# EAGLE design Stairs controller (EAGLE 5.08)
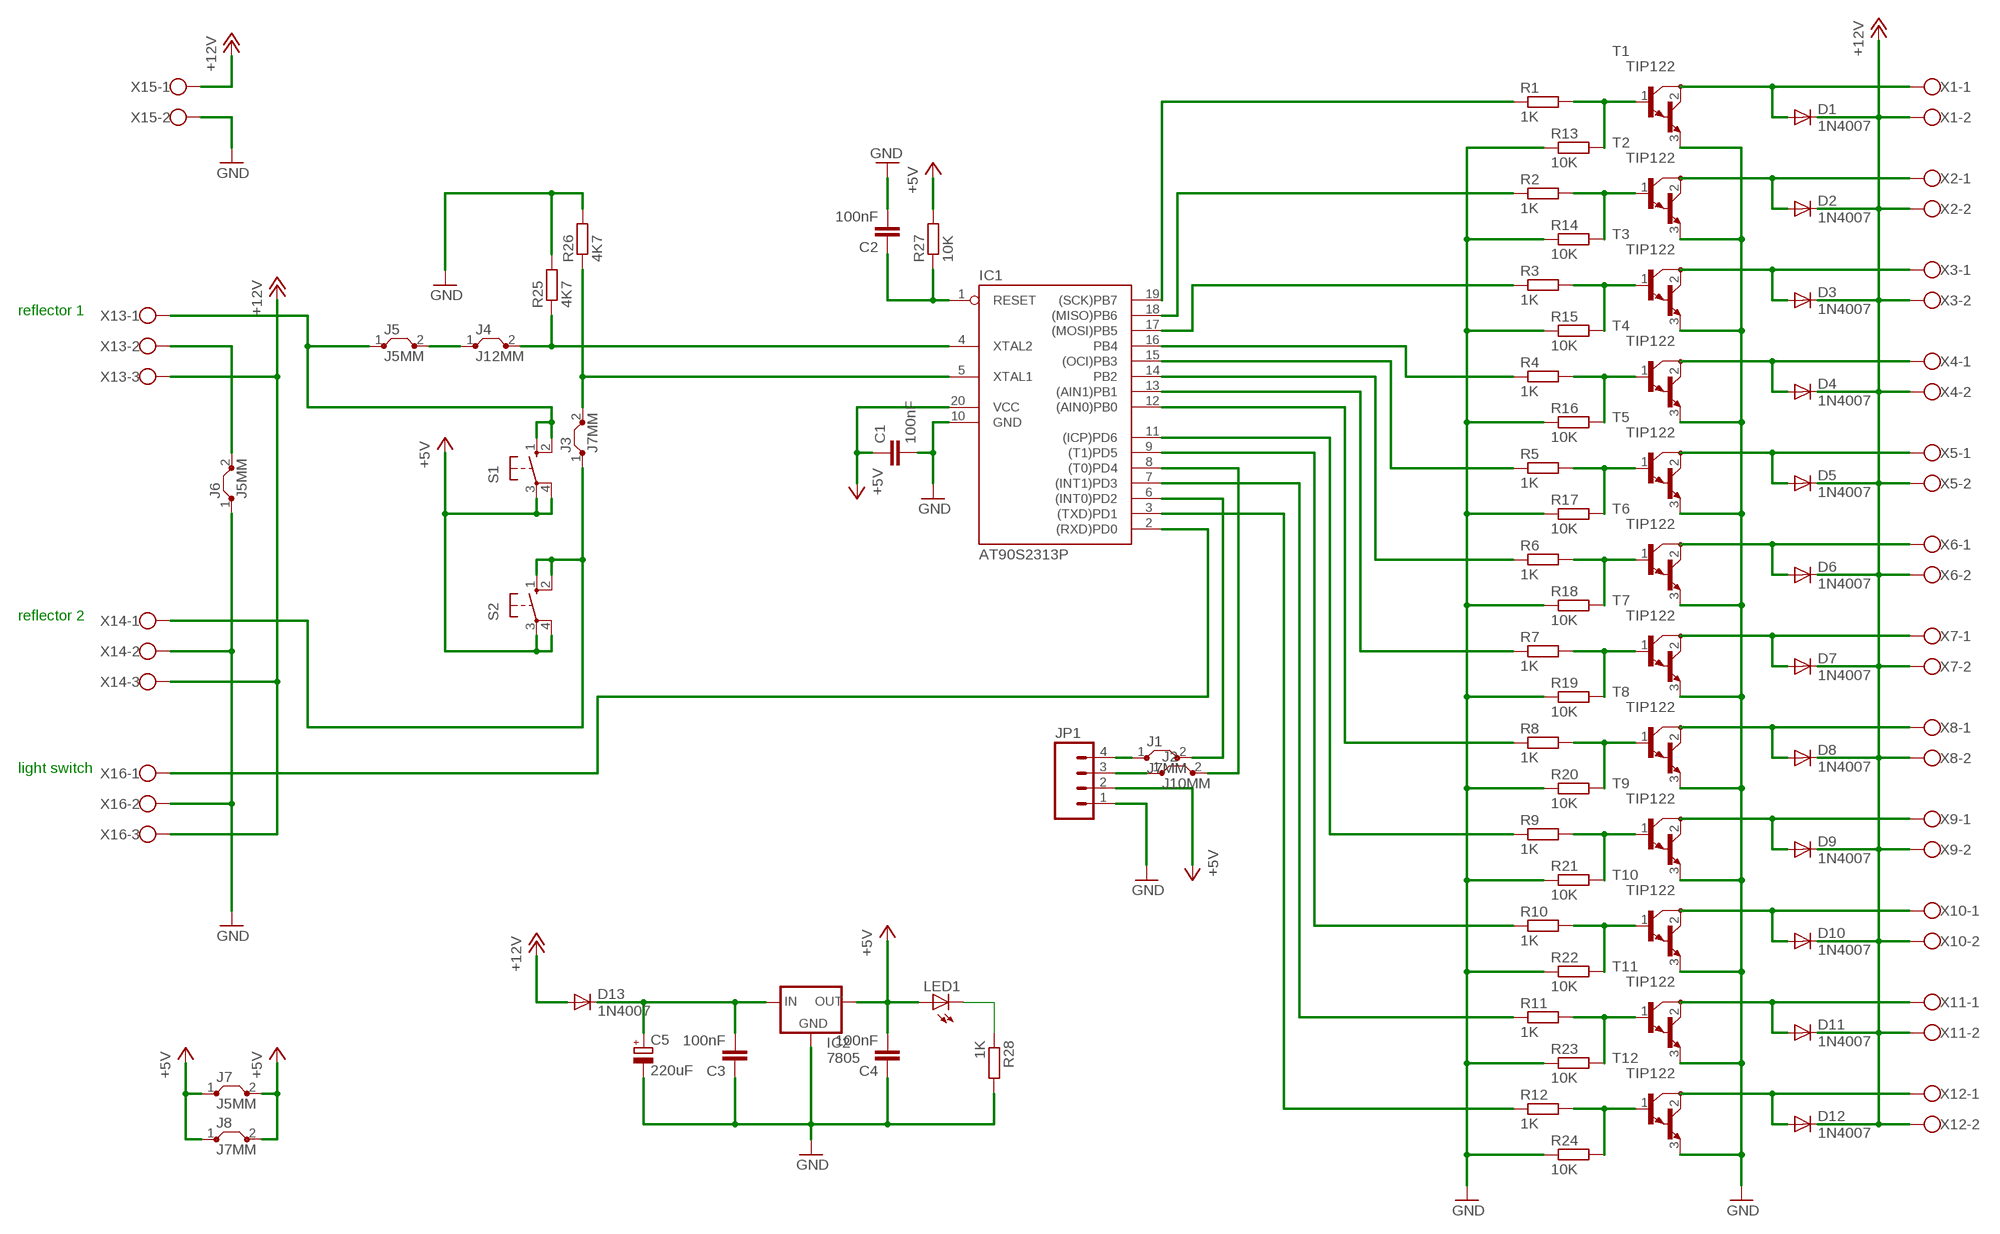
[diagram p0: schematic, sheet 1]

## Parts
C1  100nF  C-EU025-025X050  [C025-025X050]
C2  100nF  C-EU025-025X050  [C025-025X050]
C3  100nF  C-EU025-025X050  [C025-025X050]
C4  100nF  C-EU025-025X050  [C025-025X050]
C5  220uF  CPOL-EUTT5D11L  [TT5D11L]
D1  1N4007  1N4004  [DO41-10]
D2  1N4007  1N4004  [DO41-10]
D3  1N4007  1N4004  [DO41-10]
D4  1N4007  1N4004  [DO41-10]
D5  1N4007  1N4004  [DO41-10]
D6  1N4007  1N4004  [DO41-10]
D7  1N4007  1N4004  [DO41-10]
D8  1N4007  1N4004  [DO41-10]
D9  1N4007  1N4004  [DO41-10]
D10  1N4007  1N4004  [DO41-10]
D11  1N4007  1N4004  [DO41-10]
D12  1N4007  1N4004  [DO41-10]
D13  1N4007  1N4004  [DO41-10]
IC1  AT90S2313P  [DIL20]
IC2  7805  V_REG_78XXSIDE  [78XXL]
J1  J7MM  [07]
J2  J10MM  [10]
J3  J7MM  [07]
J4  J12MM  [12]
J5  J5MM  [05]
J6  J5MM  [05]
J7  J5MM  [05]
J8  J7MM  [07]
JP1  M04LONGPADS  [1X04_LONGPADS]
LED1  LED5MM  [LED5MM]
R1  1K  R-EU_0207/10  [0207/10]
R2  1K  R-EU_0207/10  [0207/10]
R3  1K  R-EU_0207/10  [0207/10]
R4  1K  R-EU_0207/10  [0207/10]
R5  1K  R-EU_0207/10  [0207/10]
R6  1K  R-EU_0207/10  [0207/10]
R7  1K  R-EU_0207/10  [0207/10]
R8  1K  R-EU_0207/10  [0207/10]
R9  1K  R-EU_0207/10  [0207/10]
R10  1K  R-EU_0207/10  [0207/10]
R11  1K  R-EU_0207/10  [0207/10]
R12  1K  R-EU_0207/10  [0207/10]
R13  10K  R-EU_0207/10  [0207/10]
R14  10K  R-EU_0207/10  [0207/10]
R15  10K  R-EU_0207/10  [0207/10]
R16  10K  R-EU_0207/10  [0207/10]
R17  10K  R-EU_0207/10  [0207/10]
R18  10K  R-EU_0207/10  [0207/10]
R19  10K  R-EU_0207/10  [0207/10]
R20  10K  R-EU_0207/10  [0207/10]
R21  10K  R-EU_0207/10  [0207/10]
R22  10K  R-EU_0207/10  [0207/10]
R23  10K  R-EU_0207/10  [0207/10]
R24  10K  R-EU_0207/10  [0207/10]
R25  4K7  R-EU_0207/10  [0207/10]
R26  4K7  R-EU_0207/10  [0207/10]
R27  10K  R-EU_0207/10  [0207/10]
R28  1K  R-EU_0207/10  [0207/10]
S1  10-XX  [B3F-10XX]
S2  10-XX  [B3F-10XX]
T1  TIP122  [TO220]
T2  TIP122  [TO220]
T3  TIP122  [TO220]
T4  TIP122  [TO220]
T5  TIP122  [TO220]
T6  TIP122  [TO220]
T7  TIP122  [TO220]
T8  TIP122  [TO220]
T9  TIP122  [TO220]
T10  TIP122  [TO220]
T11  TIP122  [TO220]
T12  TIP122  [TO220]
X1  W237-102  [W237-102]
X2  W237-102  [W237-102]
X3  W237-102  [W237-102]
X4  W237-102  [W237-102]
X5  W237-102  [W237-102]
X6  W237-102  [W237-102]
X7  W237-102  [W237-102]
X8  W237-102  [W237-102]
X9  W237-102  [W237-102]
X10  W237-102  [W237-102]
X11  W237-102  [W237-102]
X12  W237-102  [W237-102]
X13  W237-103  [W237-103]
X14  W237-103  [W237-103]
X15  W237-02P  [W237-132]
X16  W237-103  [W237-103]

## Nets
+5V: C1.1 C4.2 IC1.20(VCC) IC2.OUT J7.1 J7.2 J8.1 J8.2 JP1.2 LED1.A R27.2 S1.3(P) S1.4(P1) S2.3(P) S2.4(P1)
+12V: D1.C D2.C D3.C D4.C D5.C D6.C D7.C D8.C D9.C D10.C D11.C D12.C D13.A X1.2 X2.2 X3.2 X4.2 X5.2 X6.2 X7.2 X8.2 X9.2 X10.2 X11.2 X12.2 X13.3 X14.3 X15.1 X16.3
GND: C1.2 C2.2 C3.1 C4.1 C5.- IC1.10(GND) IC2.GND J6.1 JP1.1 R13.1 R14.1 R15.1 R16.1 R17.1 R18.1 R19.1 R20.1 R21.1 R22.1 R23.1 R24.1 R25.2 R26.2 R28.2 T1.3(E) T2.3(E) T3.3(E) T4.3(E) T5.3(E) T6.3(E) T7.3(E) T8.3(E) T9.3(E) T10.3(E) T11.3(E) T12.3(E) X14.2 X15.2 X16.2
N$1: R1.2 R13.2 T1.1(B)
N$2: R2.2 R14.2 T2.1(B)
N$3: R3.2 R15.2 T3.1(B)
N$4: R4.2 R16.2 T4.1(B)
N$5: R5.2 R17.2 T5.1(B)
N$6: R6.2 R18.2 T6.1(B)
N$7: R7.2 R19.2 T7.1(B)
N$8: R8.2 R20.2 T8.1(B)
N$9: R9.2 R21.2 T9.1(B)
N$10: R10.2 R22.2 T10.1(B)
N$11: R11.2 R23.2 T11.1(B)
N$12: R12.2 R24.2 T12.1(B)
N$13: D1.A T1.2(C) X1.1
N$14: D12.A T12.2(C) X12.1
N$15: D11.A T11.2(C) X11.1
N$16: D10.A T10.2(C) X10.1
N$17: D9.A T9.2(C) X9.1
N$18: D2.A T2.2(C) X2.1
N$19: D3.A T3.2(C) X3.1
N$20: D4.A T4.2(C) X4.1
N$21: D5.A T5.2(C) X5.1
N$22: D6.A T6.2(C) X6.1
N$23: D7.A T7.2(C) X7.1
N$24: D8.A T8.2(C) X8.1
N$26: IC1.19((SCK)PB7) R1.1
N$27: IC1.18((MISO)PB6) R2.1
N$28: IC1.17((MOSI)PB5) R3.1
N$29: IC1.16(PB4) R4.1
N$30: IC1.15((OCI)PB3) R5.1
N$31: IC1.14(PB2) R6.1
N$32: IC1.13((AIN1)PB1) R7.1
N$33: IC1.12((AIN0)PB0) R8.1
N$34: IC1.11((ICP)PD6) R9.1
N$35: J4.1 J5.2
N$36: IC1.5(XTAL1) J3.2 R26.1
N$37: C2.1 IC1.1(RESET) R27.1
N$38: C3.2 C5.+ D13.C IC2.IN
N$39: IC1.6((INT0)PD2) J1.2
N$40: IC1.8((T0)PD4) J2.2
N$41: LED1.K(C) R28.1
N$42: IC1.9((T1)PD5) R10.1
N$43: IC1.7((INT1)PD3) R11.1
N$44: IC1.3((TXD)PD1) R12.1
N$45: IC1.2((RXD)PD0) X16.1
N$46: J1.1 JP1.4
N$47: J2.1 JP1.3
N$48: J3.1 S2.1(S) S2.2(S1) X14.1
N$49: IC1.4(XTAL2) J4.2 R25.1
N$50: J6.2 X13.2
N$51: J5.1 S1.1(S) S1.2(S1) X13.1

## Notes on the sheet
- reflector 1
- reflector 2
- light switch

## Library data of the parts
C1-C4 = rcl:C-EU: CAPACITOR, European symbol
C5 = rcl:CPOL-EU: POLARIZED CAPACITOR, European symbol
D1-D13 = diode:1N4004: DIODE
IC1 = atmel:AT90S2313: MICROCONTROLLER 2 Kbytes FLASH 128 bytes SRAM 128 bytes EEPROM UART
IC2 = SparkFun:V_REG_78XX: Voltage Regulator Standard 7805 5V regulator. IGO (Input Ground Output). Spark Fun Electronics SKU : COM-00107
J1-J8 = jumper:J: Bridge
JP1 = SparkFun:M04: Header 4 Standard 4-pin 0.1" header. Use with straight break away headers (SKU : PRT-00116), right angle break away headers (PRT-00553), swiss pins (PRT-00743), machine pins (PRT-00117), and female headers (PRT-00115). Molex polarized connector foot print use with SKU : PRT-08231 with associated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
LED1 = led:LED: LED
R1-R28 = rcl:R-EU_: RESISTOR, European symbol
S1 S2 = switch-omron:10-XX: OMRON SWITCH
T1-T12 = transistor:TIP122: NPN BIPOLAR DARLINGTON TRANSISTOR
X1-X12 = con-wago-500:W237-102: WAGO SCREW CLAMP
X13 X14 X16 = con-wago-500:W237-103: WAGO SCREW CLAMP
X15 = con-wago-508:W237-02P: WAGO SREW CLAMP

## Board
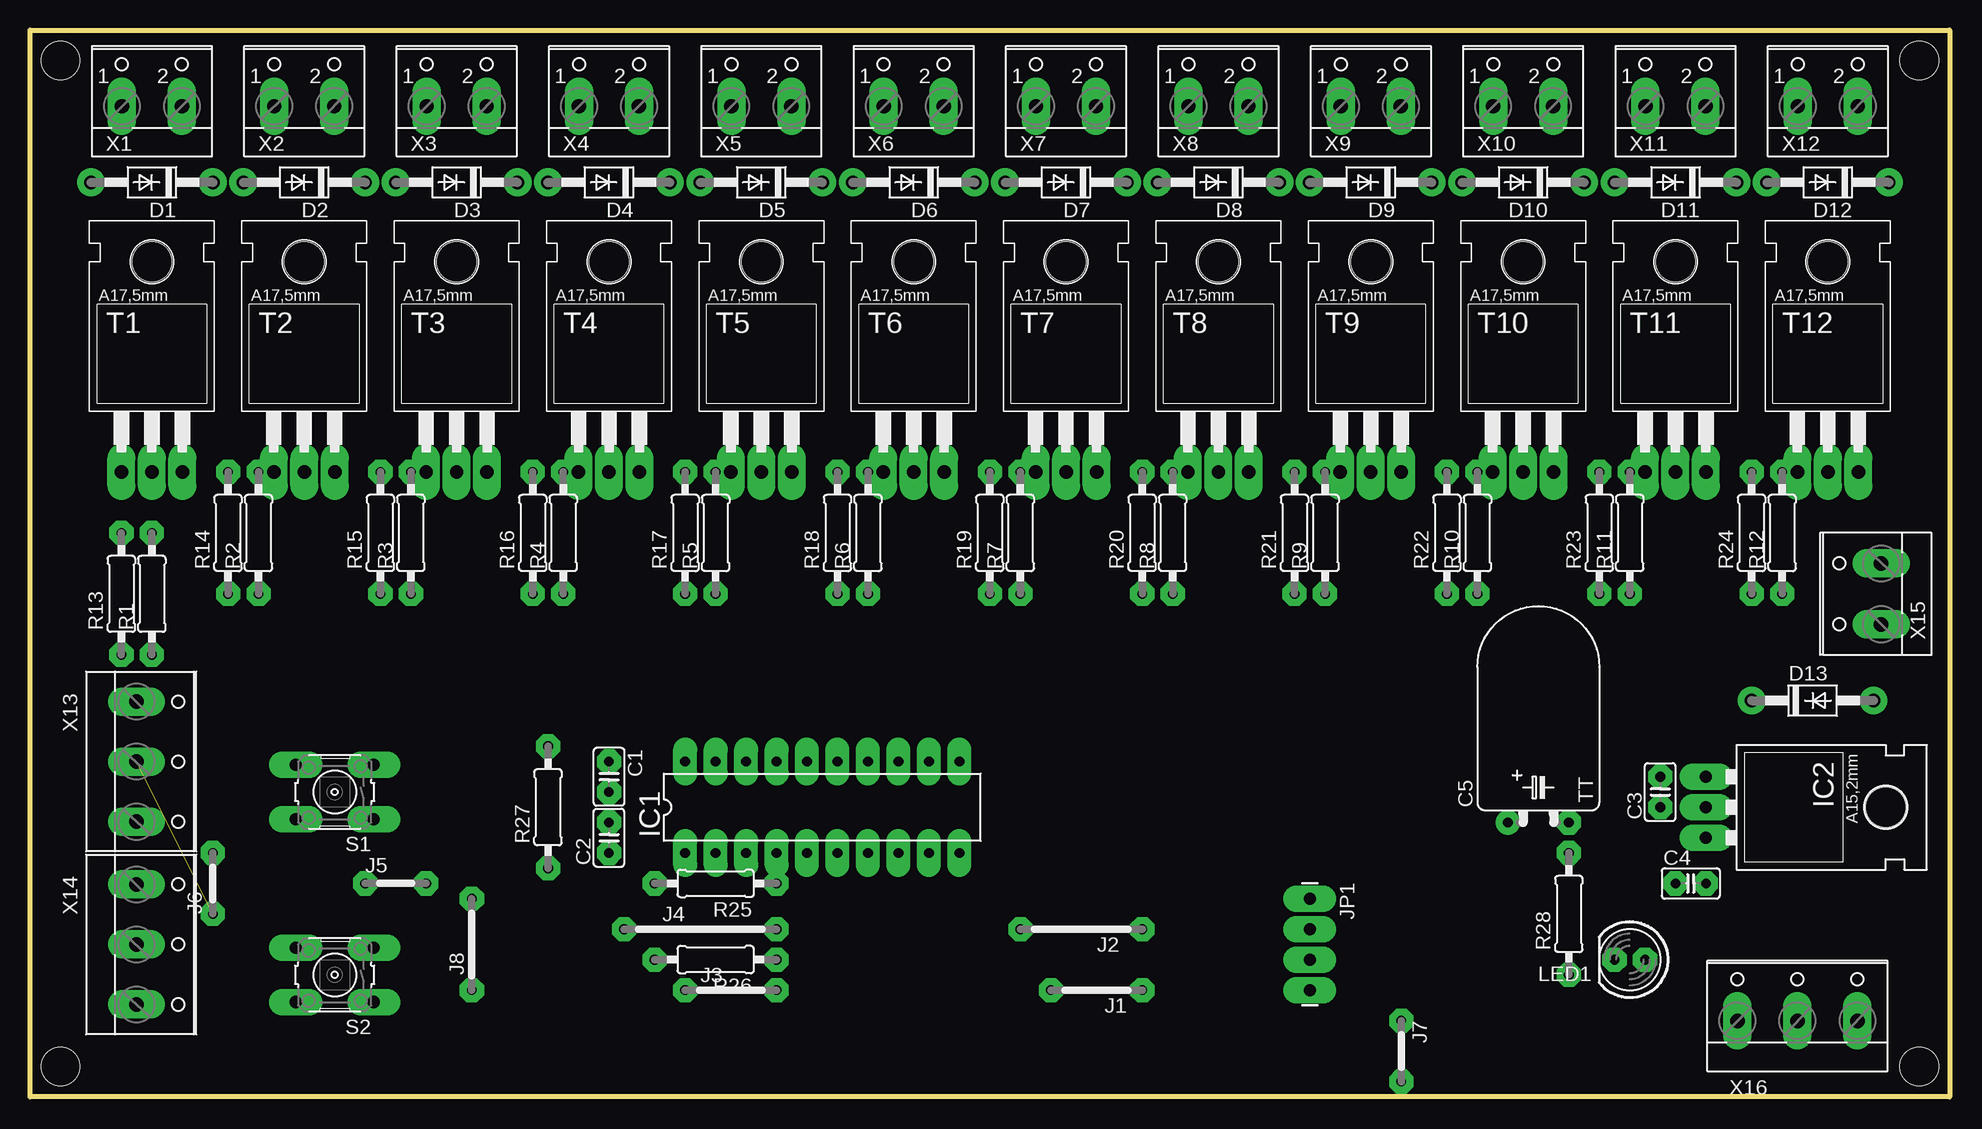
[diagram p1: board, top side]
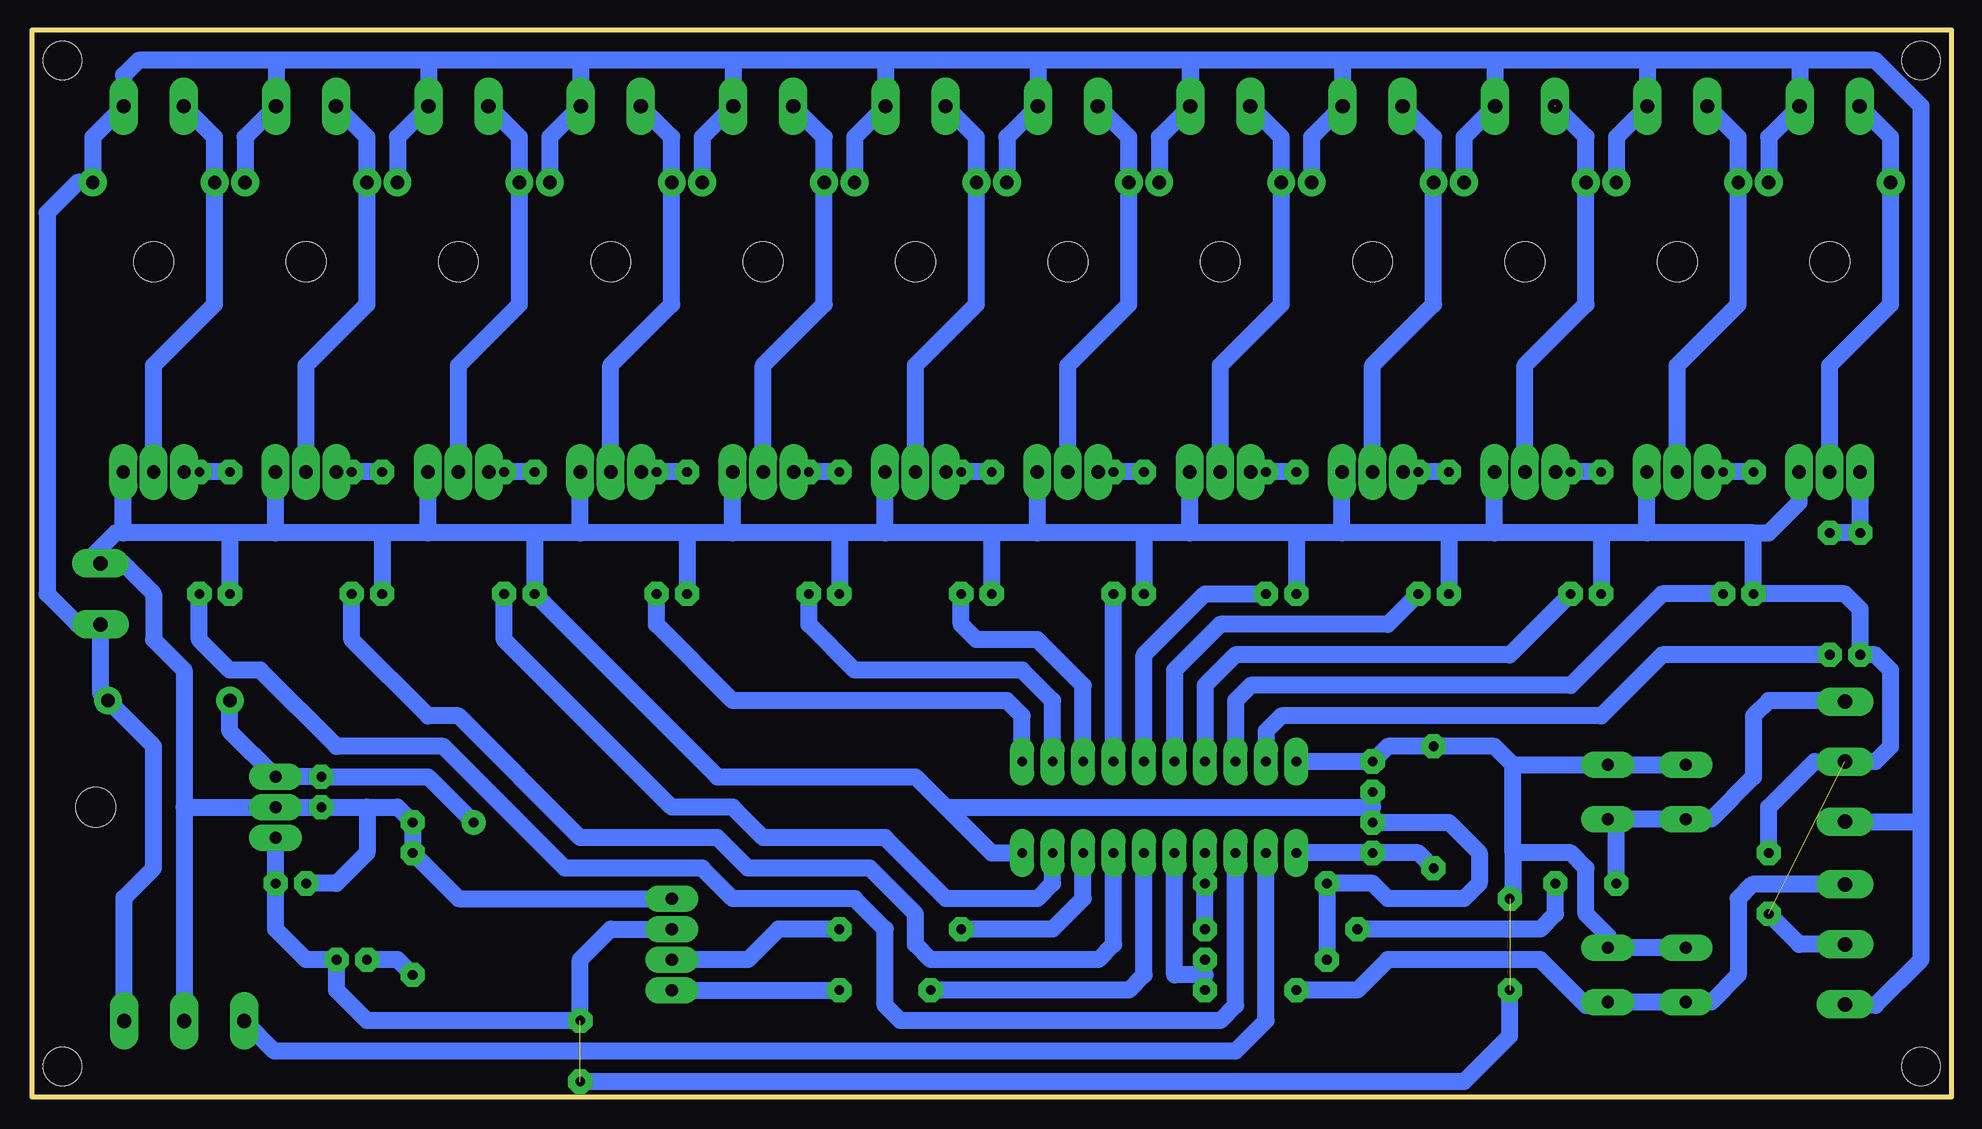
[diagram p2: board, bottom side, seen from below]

Size 160.02 x 88.9 mm. Coordinates in mm from the lower left corner, seen from the top.
Outline: 0,0 0,88.9 160.02,88.9 160.02,0 0,0
Copper layers (1*16): Top 1mm / dielectric 1.5mm / Bottom 1mm
Design rules "DRC settings middle": minimum track width 1.2mm, minimum drill 24mil, track to track 0.4mm, track to pad 0.4mm, pad to pad 0.4mm, via to via 0.4mm, smd to smd 8mil, copper to edge 0.5mm, drill to drill 0.5mm, minimum pad ring 0.6mm, minimum via ring 1mm, stop-mask expansion 4mil, vias tented up to drill 0mil, thermal gap 10mil
Holes 3.2 mm at 2.54,86.36 157.48,86.36 157.48,2.54 2.54,2.54

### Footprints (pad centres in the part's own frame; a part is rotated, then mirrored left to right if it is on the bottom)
C025-025X050 = drill 0.813 octagon: 1 -1.27,0; 2 1.27,0
TT5D11L = drill 0.813 pad 1.6 round: + -2.54,0 | drill 0.813 pad 1.6 octagon: - 2.54,0
DO41-10 = drill 1.118 round: A 5.08,0; C -5.08,0
DIL20 = drill 0.813 long: 1 -11.43,-3.81; 2 -8.89,-3.81; 3 -6.35,-3.81; 4 -3.81,-3.81; 5 -1.27,-3.81; 6 1.27,-3.81; 7 3.81,-3.81; 8 6.35,-3.81; 9 8.89,-3.81; 10 11.43,-3.81; 11 11.43,3.81; 12 8.89,3.81; 13 6.35,3.81; 14 3.81,3.81; 15 1.27,3.81; 16 -1.27,3.81; 17 -3.81,3.81; 18 -6.35,3.81; 19 -8.89,3.81; 20 -11.43,3.81
78XXL = drill 1.016 long: GND 0,-3.81; IN -2.54,-3.81; OUT 2.54,-3.81 | hole 3.302: 0,11.176
07 = drill 0.813 pad 1.6 octagon: 1 -3.81,0; 2 3.81,0
10 = drill 0.813 pad 1.6 octagon: 1 -5.08,0; 2 5.08,0
12 = drill 0.813 pad 1.6 octagon: 1 -6.35,0; 2 6.35,0
05 = drill 0.813 pad 1.6 octagon: 1 -2.54,0; 2 2.54,0
1X04_LONGPADS = drill 1.016 pad 1.88 long: 1 0,0; 2 2.54,0; 3 5.08,0; 4 7.62,0
LED5MM = drill 0.813 octagon: A -1.27,0; K 1.27,0
0207/10 = drill 0.813 octagon: 1 -5.08,0; 2 5.08,0
B3F-10XX = drill 1.016 long: 1 -3.251,2.261; 2 3.251,2.261; 3 -3.251,-2.261; 4 3.251,-2.261
TO220 = drill 1.118 long: 1 -2.54,-6.35; 2 0,-6.35; 3 2.54,-6.35 | hole 3.302: 0,11.176
W237-102 = drill 1.194 long: 1 -2.5,-1.27; 2 2.5,-1.27
W237-103 = drill 1.194 long: 1 -5,-1.29; 2 0,-1.29; 3 5,-1.29
W237-132 = drill 1.194 long: 1 -2.54,-0.635; 2 2.54,-0.635

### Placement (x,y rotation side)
C1  48.26,26.67 270 top
C2  48.26,21.59 90 top
C3  135.89,25.4 90 top
C4  138.43,17.78 0 top
C5  125.73,22.86 0 top
D1  10.16,76.2 180 top
D2  22.86,76.2 180 top
D3  35.56,76.2 180 top
D4  48.26,76.2 180 top
D5  60.96,76.2 180 top
D6  73.66,76.2 180 top
D7  86.36,76.2 180 top
D8  99.06,76.2 180 top
D9  111.76,76.2 180 top
D10  124.46,76.2 180 top
D11  137.16,76.2 180 top
D12  149.86,76.2 180 top
D13  148.59,33.02 0 top
IC1  66.04,24.13 0 top
IC2  143.51,24.13 270 top
J1  88.9,8.89 180 top
J2  87.63,13.97 180 top
J3  58.42,8.89 0 top
J4  55.88,13.97 0 top
J5  30.48,17.78 0 top
J6  15.24,17.78 90 top
J7  114.3,3.81 270 top
J8  36.83,12.7 90 top
JP1  106.68,16.51 270 top
LED1  133.35,11.43 180 top
R1  10.16,41.91 90 top
R2  19.05,46.99 90 top
R3  31.75,46.99 90 top
R4  44.45,46.99 90 top
R5  57.15,46.99 90 top
R6  69.85,46.99 90 top
R7  82.55,46.99 90 top
R8  95.25,46.99 90 top
R9  107.95,46.99 90 top
R10  120.65,46.99 90 top
R11  133.35,46.99 90 top
R12  146.05,46.99 90 top
R13  7.62,41.91 90 top
R14  16.51,46.99 90 top
R15  29.21,46.99 90 top
R16  41.91,46.99 90 top
R17  54.61,46.99 90 top
R18  67.31,46.99 90 top
R19  80.01,46.99 90 top
R20  92.71,46.99 90 top
R21  105.41,46.99 90 top
R22  118.11,46.99 90 top
R23  130.81,46.99 90 top
R24  143.51,46.99 90 top
R25  57.15,17.78 180 top
R26  57.15,11.43 180 top
R27  43.18,24.13 90 top
R28  128.27,15.24 90 top
S1  25.4,25.4 180 top
S2  25.4,10.16 180 top
T1  10.16,58.42 0 top
T2  22.86,58.42 0 top
T3  35.56,58.42 0 top
T4  48.26,58.42 0 top
T5  60.96,58.42 0 top
T6  73.66,58.42 0 top
T7  86.36,58.42 0 top
T8  99.06,58.42 0 top
T9  111.76,58.42 0 top
T10  124.46,58.42 0 top
T11  137.16,58.42 0 top
T12  149.86,58.42 0 top
X1  10.16,83.82 0 top
X2  22.86,83.82 0 top
X3  35.56,83.82 0 top
X4  48.26,83.82 0 top
X5  60.96,83.82 0 top
X6  73.66,83.82 0 top
X7  86.36,83.82 0 top
X8  99.06,83.82 0 top
X9  111.76,83.82 0 top
X10  124.46,83.82 0 top
X11  137.16,83.82 0 top
X12  149.86,83.82 0 top
X13  10.16,27.94 270 top
X14  10.16,12.7 270 top
X15  153.67,41.91 90 top
X16  147.32,7.62 0 top

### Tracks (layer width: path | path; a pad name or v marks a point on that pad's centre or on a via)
+5V  (2 unrouted)
  Bottom 1.27: 36.55,27.66 36.83,27.94
  Bottom 1.422: IC2.OUT C4.2 139.7,13.97 137.16,11.43 LED1.A 134.62,8.89 132.08,6.35 J7.1 114.3,11.43 111.76,13.97 JP1.2 | J7.2 40.64,1.27 36.83,5.08 J8.1 | IC1.20 C1.1 46.99,29.21 R27.2 38.1,29.21 36.55,27.66 | 36.55,20.32 36.55,27.66 | 36.55,20.32 36.55,16.79 J8.2 | S1.4 S1.3 36.55,27.66 | S2.4 S2.3 28.65,13.41 30.48,15.24 30.48,19.05 31.75,20.32 36.55,20.32
+12V
  Bottom 1.016: D13.A 153.69,33
  Bottom 1.27: 8.79,22.86 X13.3 | 12.7,86.36 12.66,86.32 | 63.5,86.36 63.46,86.32 | 156.21,39.37 X15.1
  Bottom 1.422: 12.66,86.32 X1.2 15.24,79.97 D1.C | 2.54,22.86 2.54,11.43 6.35,7.62 8.79,7.62 X14.3 | 2.54,22.86 2.54,82.55 6.35,86.36 12.7,86.36 25.4,86.36 | 2.54,22.86 8.79,22.86 | 25.4,86.36 38.1,86.36 | 38.1,86.36 50.8,86.36 | 50.8,86.36 63.5,86.36 | 63.5,86.36 76.2,86.36 | 76.2,86.36 88.9,86.36 | 88.9,86.36 101.6,86.36 | 101.6,86.36 114.3,86.36 | 114.3,86.36 127,86.36 | 127,86.36 139.7,86.36 | 139.7,86.36 151.13,86.36 152.36,85.13 X12.2 154.94,79.97 D12.C 156.21,76.2 158.75,73.66 158.75,41.91 156.21,39.37 | 25.4,86.36 25.36,86.32 X2.2 27.94,79.97 D2.C | 38.1,86.36 38.06,86.32 X3.2 40.64,79.97 D3.C | 63.46,86.32 X5.2 | 139.7,86.36 139.66,86.32 X11.2 142.24,79.97 D11.C | 50.8,86.36 50.76,86.32 X4.2 53.34,79.97 D4.C | D5.C 66.04,79.97 X5.2 | X5.2 63.5,82.55 63.5,86.36 | D6.C 78.74,79.97 X6.2 76.16,86.32 76.2,86.36 | D7.C 91.44,79.97 X7.2 88.86,86.32 88.9,86.36 | 101.6,86.36 101.56,86.32 X8.2 104.14,79.97 D8.C | 114.3,86.36 114.26,86.32 X9.2 116.84,79.97 D9.C | 127,86.36 126.96,86.32 X10.2 129.54,79.97 D10.C | X16.3 152.32,16.59 149.86,19.05 149.86,29.21 D13.A 154.31,33.66 X15.1
GND  (1 unrouted)
  Bottom 1.27: 154.94,45.09 X15.2 152.4,44.45 | 48.26,24.13 C2.2
  Bottom 1.422: T1.3 12.7,49.53 15.24,46.99 16.51,46.99 | 16.51,46.99 25.4,46.99 | 25.4,46.99 29.21,46.99 | 29.21,46.99 38.1,46.99 | 38.1,46.99 41.91,46.99 | 41.91,46.99 50.8,46.99 | 50.8,46.99 54.61,46.99 | 54.61,46.99 63.5,46.99 | 63.5,46.99 67.31,46.99 | 67.31,46.99 76.2,46.99 | 76.2,46.99 80.01,46.99 | 80.01,46.99 88.9,46.99 | 88.9,46.99 92.71,46.99 | 92.71,46.99 101.6,46.99 | 101.6,46.99 105.41,46.99 | 105.41,46.99 114.3,46.99 | 114.3,46.99 118.11,46.99 | 118.11,46.99 127,46.99 | 127,46.99 130.81,46.99 | 130.81,46.99 139.7,46.99 | 139.7,46.99 143.51,46.99 | 143.51,46.99 152.4,46.99 | 152.4,46.99 153.03,46.99 154.94,45.09 | 152.4,46.99 T12.3 | 139.7,46.99 T11.3 | 127,46.99 T10.3 | 114.3,46.99 T9.3 | 101.6,46.99 T8.3 | 88.9,46.99 T7.3 | 76.2,46.99 T6.3 | 63.5,46.99 T5.3 | 50.8,46.99 T4.3 | 38.1,46.99 T3.3 | 25.4,46.99 T2.3 | 16.51,46.99 R14.1 8.89,41.91 7.62,40.64 R13.1 6.35,36.83 5.08,35.56 5.08,29.21 6.35,27.94 8.89,27.94 | 130.81,46.99 R23.1 | 143.51,46.99 R24.1 | 118.11,46.99 R22.1 102.87,26.67 86.36,26.67 83.82,24.13 | 105.41,46.99 R21.1 | 92.71,46.99 R20.1 | 80.01,46.99 R19.1 | 67.31,46.99 R18.1 | 54.61,46.99 R17.1 | 41.91,46.99 R16.1 | 29.21,46.99 R15.1 | IC1.10 80.01,20.32 83.82,24.13 | C1.2 48.26,24.13 83.82,24.13 | 147.32,24.13 147.32,35.56 149.86,38.1 149.86,41.91 152.4,44.45 | 147.32,24.13 X16.2 | 147.32,24.13 IC2.GND C3.1 132.08,24.13 | 132.08,24.13 129.54,24.13 C5.- R28.2 124.46,16.51 JP1.1 | C4.1 134.62,17.78 132.08,20.32 132.08,24.13 | C2.2 41.91,22.86 39.37,20.32 39.37,17.78 40.64,16.51 46.99,16.51 48.26,17.78 R25.2 R26.2 | X14.2 12.7,12.7 J6.1
N$1
  Bottom 1.422: R1.2 R13.2 T1.1
N$2
  Bottom 1.27: R2.2 T2.1
  Bottom 1.422: R14.2 R2.2
N$3
  Bottom 1.27: R3.2 T3.1
  Bottom 1.422: R15.2 R3.2
N$4
  Bottom 1.27: R4.2 T4.1
  Bottom 1.422: R16.2 R4.2
N$5
  Bottom 1.27: R5.2 T5.1
  Bottom 1.422: R17.2 R5.2
N$6
  Bottom 1.27: R6.2 T6.1
  Bottom 1.422: R18.2 R6.2
N$7
  Bottom 1.27: R7.2 T7.1
  Bottom 1.422: R19.2 R7.2
N$8
  Bottom 1.27: R8.2 T8.1
  Bottom 1.422: R20.2 R8.2
N$9
  Bottom 1.27: R9.2 T9.1
  Bottom 1.422: R21.2 R9.2
N$10
  Bottom 1.27: R10.2 T10.1
  Bottom 1.422: R22.2 R10.2
N$11
  Bottom 1.27: R11.2 T11.1
  Bottom 1.422: R23.2 R11.2
N$12
  Bottom 1.27: R12.2 T12.1
  Bottom 1.422: R24.2 R12.2
N$13
  Bottom 1.422: T1.2 10.16,60.96 5.08,66.04 D1.A 5.08,79.97 X1.1
N$14
  Bottom 1.422: T12.2 149.86,60.96 144.78,66.04 D12.A 144.78,79.97 X12.1
N$15
  Bottom 1.422: T11.2 137.16,60.96 132.08,66.04 D11.A 132.08,79.97 X11.1
N$16
  Bottom 1.422: T10.2 124.46,60.96 119.38,66.04 D10.A 119.38,79.97 X10.1
N$17
  Bottom 1.422: T9.2 111.76,60.96 106.68,66.04 D9.A 106.68,79.97 X9.1
N$18
  Bottom 1.422: T2.2 22.86,60.96 17.78,66.04 D2.A 17.78,79.97 X2.1
N$19  (1 unrouted)
  Bottom 1.422: T3.2 35.56,60.96 30.48,66.04 D3.A 30.48,80.01 33.02,82.55
N$20
  Bottom 1.422: T4.2 48.26,60.96 43.18,66.04 D4.A 43.18,79.97 X4.1
N$21
  Bottom 1.422: T5.2 60.96,60.96 55.88,66.04 D5.A 55.88,79.97 X5.1
N$22
  Bottom 1.422: T6.2 73.66,60.96 68.58,66.04 D6.A 68.58,79.97 X6.1
N$23
  Bottom 1.422: T7.2 86.36,60.96 81.28,66.04 D7.A 81.28,79.97 X7.1
N$24
  Bottom 1.422: T8.2 99.06,60.96 93.98,66.04 D8.A 93.98,79.97 X8.1
N$26
  Bottom 1.422: R1.1 24.13,36.83 29.21,31.75 55.88,31.75 57.15,30.48 IC1.19
N$27
  Bottom 1.422: R2.1 24.13,41.91 31.75,34.29 58.42,34.29 59.69,33.02 IC1.18
N$28
  Bottom 1.422: R3.1 36.83,36.83 59.69,36.83 62.23,34.29 IC1.17
N$29
  Bottom 1.422: R4.1 46.99,39.37 60.96,39.37 64.77,35.56 IC1.16
N$30
  Bottom 1.422: R5.1 62.23,41.91 67.31,36.83 IC1.15
N$31
  Bottom 1.422: IC1.14 R6.1
N$32
  Bottom 1.422: R7.1 82.55,39.37 81.28,38.1 76.2,38.1 72.39,34.29 IC1.13
N$33
  Bottom 1.422: IC1.12 74.93,33.02 77.47,35.56 91.44,35.56 95.25,39.37 R8.1
N$34
  Bottom 1.422: IC1.11 77.47,31.75 78.74,33.02 101.6,33.02 107.95,39.37 R9.1
N$35
  Bottom 1.422: J4.1 34.29,13.97 33.02,15.24 J5.2
N$36
  Bottom 1.27: J3.2 62.23,10.16 R26.1
  Bottom 1.422: 62.23,10.16 64.77,10.16 IC1.5
N$37
  Bottom 1.422: IC1.1 C2.1 44.45,20.32 R27.1
N$38
  Bottom 1.422: D13.C 143.51,30.48 IC2.IN C3.2 127,26.67 C5.+
N$39
  Bottom 1.422: IC1.6 67.31,10.16 68.58,8.89 J1.2
N$40
  Bottom 1.422: IC1.8 72.39,16.51 74.93,13.97 J2.2
N$41
  Bottom 1.422: LED1.K 129.54,11.43 R28.1
N$42
  Bottom 1.422: R10.1 120.65,38.1 106.68,24.13 101.6,24.13 99.06,21.59 88.9,21.59 83.82,16.51 76.2,16.51 74.93,17.78 IC1.9
N$43
  Bottom 1.422: IC1.7 69.85,12.7 71.12,11.43 85.09,11.43 86.36,12.7 86.36,15.24 90.17,19.05 100.33,19.05 102.87,21.59 114.3,21.59 124.46,31.75 127,31.75 133.35,38.1 R11.1
N$44
  Bottom 1.422: IC1.3 59.69,7.62 60.96,6.35 87.63,6.35 88.9,7.62 88.9,13.97 91.44,16.51 101.6,16.51 104.14,19.05 115.57,19.05 125.73,29.21 134.62,29.21 140.97,35.56 143.51,35.56 146.05,38.1 R12.1
N$45
  Bottom 1.27: X16.1 142.22,6.33
  Bottom 1.422: IC1.2 57.15,6.35 59.69,3.81 139.8,3.81 X16.1
N$46
  Bottom 1.422: JP1.4 J1.1
N$47
  Bottom 1.422: JP1.3 100.33,11.43 97.79,13.97 J2.1
N$48
  Bottom 1.27: 20.04,7.9 S2.2 | X14.1 8.95,17.78
  Bottom 1.422: J3.1 49.53,8.89 46.99,11.43 34.29,11.43 30.48,7.62 27.66,7.62 S2.1 S2.2 | X14.1 16.59,17.7 17.78,16.51 17.78,10.16 20.04,7.9
N$49
  Bottom 1.016: R25.1 IC1.4
  Bottom 1.422: J4.2 R25.1
N$50
  Bottom 1.422: X13.2 11.43,27.94 15.24,24.13 J6.2
N$51
  Bottom 1.27: 20.04,23.14 S1.2
  Bottom 1.422: S1.2 S1.1 27.94,22.43 J5.1 | 20.04,23.14 16.51,26.67 16.51,31.75 15.24,33.02 8.95,33.02 X13.1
